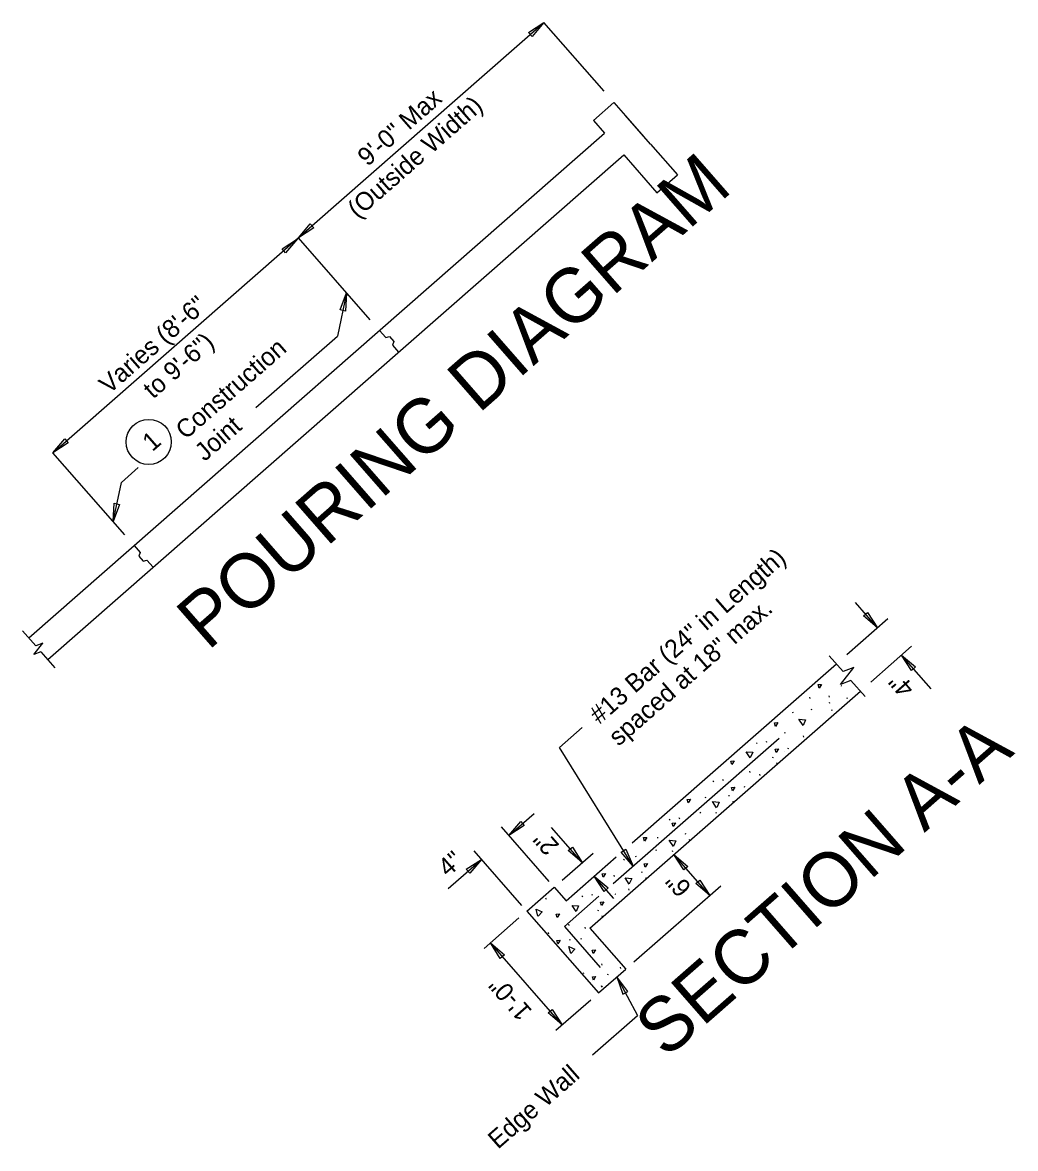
# Model space of a CAD drawing. Extents: x 1970965 to 1971298, y 796258 to 796581.
# Drawn here: x 1971126.1 to 1971180.9, y 796413.5 to 796475.6 of the extents above; entities that cross this region are included whole.
import ezdxf

# ---------------------------------------------------------------- set-up
doc = ezdxf.new("R2010")
doc.units = 0
for name, color, linetype in [('BR_AUTO DIMENSION', 7, 'Continuous'), ('BR_CENTER LINES', 7, 'Continuous'), ('BR_CONCRETE', 7, 'Continuous'), ('BR_REBAR', 7, 'Continuous'), ('BR_TABLE LINES', 7, 'Continuous'), ('BR_TEXT', 7, 'Continuous')]:
    doc.layers.add(name, color=color, linetype=linetype)

msp = doc.modelspace()

# ---------------------------------------------------------------- linework, layer by layer
at = {"layer": 'BR_AUTO DIMENSION'}
for p, q in [((1971127.801, 796451.854), (1971154.876, 796475.566)), ((1971158.196, 796471.776), (1971154.876, 796475.566)), ((1971145.302, 796459.185), (1971141.339, 796463.71)), ((1971143.998, 796460.674), (1971143.491, 796458.283)), ((1971138.998, 796454.348), (1971143.491, 796458.283)), ((1971131.764, 796447.328), (1971127.801, 796451.854)), ((1971131.578, 796450.229), (1971132.513, 796451.048)), ((1971131.119, 796448.066), (1971131.578, 796450.229)), ((1971173.269, 796442.213), (1971172.054, 796443.6)), ((1971173.826, 796442.701), (1971171.573, 796440.727)), ((1971175.144, 796441.196), (1971172.89, 796439.223)), ((1971176.22, 796438.843), (1971174.586, 796440.708)), ((1971155.74, 796435.623), (1971156.99, 796436.717)), ((1971159.796, 796429.084), (1971155.74, 796435.623)), ((1971152.94, 796430.773), (1971154.33, 796431.99)), ((1971155.165, 796428.232), (1971152.53, 796431.241)), ((1971156.988, 796429.283), (1971155.297, 796431.213)), ((1971153.661, 796426.915), (1971151.026, 796429.924)), ((1971155.883, 796428.315), (1971157.584, 796429.804)), ((1971149.594, 796427.842), (1971151.436, 796429.455)), ((1971164.018, 796427.466), (1971162.042, 796429.722)), ((1971158.728, 796427.296), (1971157.647, 796428.53)), ((1971159.835, 796423.802), (1971164.632, 796428.004)), ((1971151.579, 796424.545), (1971153.5, 796426.228)), ((1971155.877, 796420.336), (1971151.925, 796424.848)), ((1971158.893, 796422.977), (1971160.036, 796420.843)), ((1971155.531, 796420.033), (1971157.452, 796421.715)), ((1971157.561, 796418.676), (1971160.036, 796420.843))]:
    msp.add_line(p, q, dxfattribs=at)
for points in [[(1971154.025, 796475.021), (1971154.876, 796475.566), (1971154.223, 796474.795)], [(1971142.19, 796464.256), (1971141.339, 796463.71), (1971141.992, 796464.482)], [(1971140.436, 796463.094), (1971141.287, 796463.64), (1971140.634, 796462.868)], [(1971143.644, 796459.727), (1971143.998, 796460.674), (1971143.937, 796459.665)], [(1971128.652, 796452.4), (1971127.801, 796451.854), (1971128.454, 796452.625)], [(1971131.473, 796449.012), (1971131.119, 796448.066), (1971131.18, 796449.075)], [(1971172.723, 796443.063), (1971173.269, 796442.212), (1971172.498, 796442.866)], [(1971175.132, 796439.857), (1971174.586, 796440.708), (1971175.358, 796440.055)], [(1971153.791, 796431.319), (1971152.94, 796430.773), (1971153.593, 796431.544)], [(1971156.442, 796430.133), (1971156.988, 796429.283), (1971156.217, 796429.936)], [(1971159.396, 796430.012), (1971159.796, 796429.084), (1971159.141, 796429.854)], [(1971150.585, 796428.91), (1971151.436, 796429.455), (1971150.783, 796428.684)], [(1971162.588, 796428.871), (1971162.042, 796429.722), (1971162.813, 796429.069)], [(1971158.193, 796427.68), (1971157.647, 796428.53), (1971158.418, 796427.877)], [(1971163.472, 796428.316), (1971164.018, 796427.466), (1971163.247, 796428.119)], [(1971152.471, 796423.997), (1971151.925, 796424.848), (1971152.696, 796424.195)], [(1971159.497, 796422.166), (1971158.893, 796422.977), (1971159.233, 796422.025)], [(1971155.331, 796421.187), (1971155.877, 796420.336), (1971155.106, 796420.989)]]:
    msp.add_lwpolyline(points, close=True, dxfattribs=at)
at = {"layer": 'BR_CENTER LINES'}
for points in [[(1971127.145, 796440.892), (1971126.76, 796440.747), (1971127.245, 796441.364), (1971126.859, 796441.218)], [(1971171.803, 796439.312), (1971171.225, 796439.094), (1971171.952, 796440.019), (1971171.374, 796439.801)]]:
    msp.add_lwpolyline(points, dxfattribs=at)
at = {"layer": 'BR_CONCRETE'}
for p, q in [((1971157.605, 796470.175), (1971158.733, 796471.163)), ((1971158.733, 796471.163), (1971160.401, 796469.258)), ((1971157.605, 796470.175), (1971158.223, 796469.469)), ((1971160.751, 796468.859), (1971159.351, 796470.457)), ((1971126.472, 796441.661), (1971158.223, 796469.469)), ((1971160.751, 796468.859), (1971162.233, 796467.166)), ((1971127.522, 796440.462), (1971159.273, 796468.27)), ((1971159.273, 796468.27), (1971161.105, 796466.178)), ((1971161.105, 796466.178), (1971162.233, 796467.166)), ((1971145.814, 796458.6), (1971146.153, 796458.213)), ((1971146.153, 796458.213), (1971146.356, 796458.266)), ((1971146.356, 796458.266), (1971146.603, 796457.984)), ((1971146.603, 796457.984), (1971146.524, 796457.79)), ((1971146.524, 796457.79), (1971146.864, 796457.402)), ((1971132.276, 796446.744), (1971132.616, 796446.356)), ((1971132.616, 796446.356), (1971132.537, 796446.162)), ((1971132.537, 796446.162), (1971132.784, 796445.88)), ((1971132.784, 796445.88), (1971132.986, 796445.933)), ((1971132.986, 796445.933), (1971133.326, 796445.546)), ((1971159.739, 796430.363), (1971171.002, 796440.227)), ((1971157.412, 796425.667), (1971172.319, 796438.723)), ((1971156.094, 796427.171), (1971158.864, 796429.597)), ((1971153.932, 796426.606), (1971155.436, 796427.923)), ((1971155.436, 796427.923), (1971156.094, 796427.171)), ((1971153.932, 796426.606), (1971157.884, 796422.093)), ((1971157.412, 796425.667), (1971159.388, 796423.411)), ((1971157.884, 796422.093), (1971159.388, 796423.411))]:
    msp.add_line(p, q, dxfattribs=at)
at = {"layer": 'BR_REBAR'}
for p, q in [((1971158.696, 796428.121), (1971167.849, 796436.137)), ((1971156.001, 796425.76), (1971157.893, 796427.417)), ((1971156.001, 796425.76), (1971157.977, 796423.504))]:
    msp.add_line(p, q, dxfattribs=at)
at = {"layer": 'BR_TABLE LINES'}
for p, q in [((1971126.129, 796442.052), (1971126.859, 796441.218)), ((1971127.145, 796440.892), (1971127.913, 796440.016)), ((1971171.374, 796439.801), (1971170.607, 796440.678)), ((1971172.581, 796438.424), (1971171.803, 796439.312))]:
    msp.add_line(p, q, dxfattribs=at)
at = {"layer": 'BR_TEXT'}
for p, q in [((1971170.613, 796438.394), (1971170.592, 796438.461)), ((1971169.553, 796438.322), (1971169.533, 796438.389)), ((1971170.636, 796438.04), (1971170.617, 796438.102)), ((1971171.613, 796438.296), (1971171.592, 796438.363)), ((1971168.618, 796437.502), (1971168.597, 796437.569)), ((1971169.648, 796437.67), (1971169.628, 796437.737)), ((1971170.708, 796437.688), (1971170.758, 796437.675)), ((1971167.173, 796435.89), (1971167.153, 796435.957)), ((1971168.177, 796436.382), (1971168.157, 796436.449)), ((1971169.206, 796436.188), (1971169.186, 796436.255)), ((1971166.592, 796435.882), (1971166.639, 796435.838)), ((1971168.302, 796435.581), (1971168.351, 796435.567)), ((1971167.463, 796435.086), (1971167.512, 796435.073)), ((1971167.729, 796434.703), (1971167.71, 796434.765)), ((1971166.243, 796434.244), (1971166.223, 796434.31)), ((1971166.8, 796434.08), (1971166.779, 796434.147)), ((1971164.185, 796433.774), (1971164.233, 796433.73)), ((1971164.767, 796433.782), (1971164.746, 796433.849)), ((1971163.751, 796432.873), (1971163.801, 796432.86)), ((1971165.056, 796432.978), (1971165.106, 796432.965)), ((1971165.895, 796433.473), (1971165.945, 796433.459)), ((1971165.323, 796432.595), (1971165.303, 796432.658)), ((1971161.779, 796431.666), (1971161.826, 796431.623)), ((1971162.36, 796431.674), (1971162.339, 796431.741)), ((1971163.517, 796431.991), (1971163.496, 796432.058)), ((1971164.393, 796431.972), (1971164.372, 796432.039)), ((1971161.123, 796430.666), (1971161.172, 796430.653)), ((1971162.65, 796430.871), (1971162.699, 796430.857)), ((1971162.916, 796430.487), (1971162.897, 796430.55)), ((1971161.082, 796429.916), (1971161.061, 796429.983)), ((1971161.986, 796429.865), (1971161.966, 796429.931)), ((1971159.271, 796429.469), (1971159.318, 796429.426)), ((1971159.953, 796429.566), (1971159.933, 796429.633)), ((1971158.774, 796428.514), (1971158.753, 796428.581)), ((1971160.243, 796428.763), (1971160.292, 796428.75)), ((1971160.509, 796428.38), (1971160.49, 796428.442)), ((1971155.009, 796427.247), (1971154.988, 796427.314)), ((1971156.965, 796427.45), (1971157.013, 796427.407)), ((1971157.547, 796427.459), (1971157.526, 796427.525)), ((1971158.777, 796427.547), (1971158.826, 796427.533)), ((1971159.58, 796427.757), (1971159.559, 796427.824)), ((1971157.836, 796426.655), (1971157.886, 796426.642)), ((1971158.103, 796426.272), (1971158.083, 796426.334)), ((1971155.14, 796425.351), (1971155.119, 796425.418)), ((1971156.274, 796425.817), (1971156.253, 796425.884)), ((1971157.173, 796425.649), (1971157.152, 796425.716)), ((1971156.268, 796425.042), (1971156.318, 796425.028)), ((1971156.945, 796425.036), (1971156.925, 796425.102)), ((1971158.081, 796423.632), (1971158.06, 796423.699)), ((1971157.077, 796423.139), (1971157.056, 796423.206)), ((1971158.368, 796423.128), (1971158.418, 796423.114)), ((1971159.11, 796423.438), (1971159.089, 796423.505))]:
    msp.add_line(p, q, dxfattribs=at)
for points in [[(1971170.045, 796438.891), (1971169.992, 796439.081), (1971170.169, 796439.094), (1971170.045, 796438.891)], [(1971171.282, 796439.004), (1971171.274, 796439.017)], [(1971171.292, 796439.024), (1971171.286, 796439.01)], [(1971170.697, 796437.302), (1971170.696, 796437.305), (1971170.699, 796437.304)], [(1971167.639, 796436.784), (1971167.586, 796436.973), (1971167.763, 796436.987), (1971167.639, 796436.784)], [(1971169.159, 796436.833), (1971168.934, 796437.175), (1971169.299, 796437.145), (1971169.163, 796436.839)], [(1971166.247, 796435.041), (1971166.022, 796435.384), (1971166.387, 796435.354), (1971166.251, 796435.048)], [(1971167.675, 796435.338), (1971167.623, 796435.528), (1971167.8, 796435.541), (1971167.675, 796435.338)], [(1971168.124, 796435.384), (1971168.123, 796435.387), (1971168.126, 796435.386)], [(1971165.232, 796434.676), (1971165.179, 796434.865), (1971165.356, 796434.879), (1971165.232, 796434.676)], [(1971165.269, 796433.23), (1971165.216, 796433.42), (1971165.393, 796433.433), (1971165.269, 796433.23)], [(1971165.884, 796433.086), (1971165.883, 796433.09), (1971165.886, 796433.088)], [(1971162.825, 796432.568), (1971162.772, 796432.758), (1971162.949, 796432.771), (1971162.825, 796432.568)], [(1971164.397, 796432.298), (1971164.172, 796432.641), (1971164.536, 796432.611), (1971164.401, 796432.304)], [(1971161.996, 796431.258), (1971161.943, 796431.448), (1971162.12, 796431.461), (1971161.996, 796431.258)], [(1971160.419, 796430.46), (1971160.366, 796430.65), (1971160.543, 796430.663), (1971160.419, 796430.46)], [(1971162.01, 796430.168), (1971161.785, 796430.511), (1971162.149, 796430.481), (1971162.013, 796430.175)], [(1971163.477, 796430.979), (1971163.476, 796430.982), (1971163.479, 796430.98)], [(1971160.455, 796429.015), (1971160.402, 796429.204), (1971160.58, 796429.218), (1971160.455, 796429.015)], [(1971158.148, 796428.471), (1971158.095, 796428.661), (1971158.272, 796428.675), (1971158.148, 796428.471)], [(1971161.07, 796428.871), (1971161.07, 796428.874), (1971161.072, 796428.873)], [(1971159.574, 796428.094), (1971159.349, 796428.436), (1971159.714, 796428.406), (1971159.578, 796428.1)], [(1971154.547, 796426.319), (1971154.452, 796426.718), (1971154.784, 796426.565), (1971154.552, 796426.324)], [(1971156.649, 796426.577), (1971156.424, 796426.92), (1971156.789, 796426.89), (1971156.653, 796426.584)], [(1971158.049, 796426.907), (1971157.996, 796427.097), (1971158.173, 796427.11), (1971158.049, 796426.907)], [(1971158.664, 796426.763), (1971158.663, 796426.766), (1971158.666, 796426.765)], [(1971155.605, 796426.245), (1971155.552, 796426.434), (1971155.729, 796426.448), (1971155.605, 796426.245)], [(1971155.642, 796424.799), (1971155.589, 796424.989), (1971155.766, 796425.002), (1971155.642, 796424.799)], [(1971156.35, 796424.26), (1971156.256, 796424.658), (1971156.588, 796424.506), (1971156.356, 796424.264)], [(1971157.589, 796424.269), (1971157.536, 796424.459), (1971157.713, 796424.472), (1971157.589, 796424.269)], [(1971157.602, 796422.797), (1971157.549, 796422.987), (1971157.726, 796423), (1971157.602, 796422.797)], [(1971158.059, 796422.416), (1971158.042, 796422.484), (1971158.105, 796422.456)]]:
    msp.add_lwpolyline(points, dxfattribs=at)
msp.add_circle((1971133.088, 796452.455), 1.244, dxfattribs=at)

# ---------------------------------------------------------------- texts
for s, height, rotation, p in [('(Outside Width)', 0.99975, 41.21202, (1971144.6, 796464.727)), ('9\'-0" Max', 0.9998, 41.21202, (1971145.148, 796467.599)), ('POURING DIAGRAM', 2.99925, 41.21202, (1971136.35, 796440.91)), ('Varies (8\'-6"', 0.99975, 41.21202, (1971130.901, 796455.056)), ('to 9\'-6")', 0.9998, 41.21202, (1971133.326, 796454.788)), ('Construction', 0.99975, 41.21202, (1971135.119, 796452.547)), ('Joint', 0.9998, 41.21202, (1971136.172, 796451.344)), ('1', 1, 41.21202, (1971133.285, 796451.886)), ('#13 Bar (24" in Length)', 0.99975, 41.21202, (1971157.933, 796436.854)), ('spaced at 18" max.', 0.99975, 41.21202, (1971158.987, 796435.651)), ('4"', 0.9997, 131.21202, (1971175.359, 796438.917)), ('SECTION A-A', 2.99925, 41.21202, (1971161.6, 796418.423)), ('2"', 0.9997, 131.21202, (1971155.766, 796430.232)), ('4"', 0.9998, 41.21202, (1971149.58, 796428.447)), ('6"', 0.9997, 131.21202, (1971163.065, 796427.929)), ('1\'-0"', 0.9997, 131.21202, (1971154.268, 796421.109)), ('Edge Wall', 0.9998, 41.21202, (1971152.34, 796413.45))]:
    msp.add_text(s, height=height, rotation=rotation, dxfattribs=at).set_placement(p)

doc.saveas('drawing.dxf')
